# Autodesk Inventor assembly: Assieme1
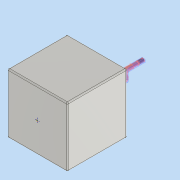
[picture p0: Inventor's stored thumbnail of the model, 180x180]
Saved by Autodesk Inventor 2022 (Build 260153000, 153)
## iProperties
Created: 2022-10
Part Number: Assieme1
Document SubType Name: Assembly
Designer: x300
Author: x300
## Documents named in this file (4)
- C:\Users\x300\Desktop\Crane hook\Assieme1.iam
- C:\Users\x300\Desktop\Crane hook\Crane hook.ipt
- C:\Users\x300\Desktop\Crane hook\peso.ipt
- C:\Users\x300\Desktop\Crane hook\gancio_2.ipt
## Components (3 placed, 3 different names)
1. Crane hook:1 — Coincidente:1, Angolo:1, Tangente:1
2. peso:1 — Coincidente:1, Angolo:1, Tangente:1, Allineato:1
3. gancio_2:1 — Allineato:1
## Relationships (4: Mate 1, Angle 1, Tangent 1, Flush 1)
- Coincidente:1 [Mate]: Crane hook:1 ↔ peso:1
- Angolo:1 [Angle]: Crane hook:1 ↔ peso:1
- Tangente:1: Crane hook:1 ↔ peso:1
- Allineato:1 [Flush]: peso:1 ↔ gancio_2:1
## Named parameters: sa_0 = 627840 mm, sa_1 = 627840 mm
